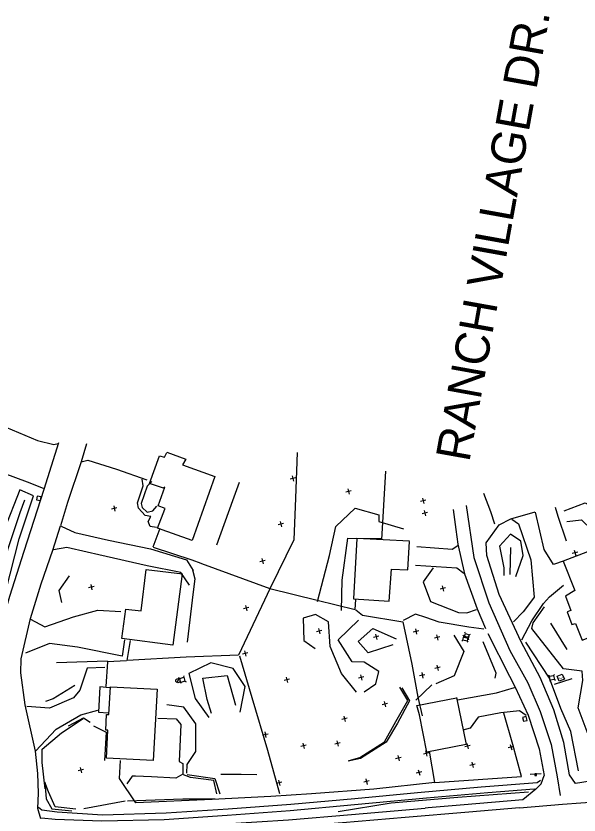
# Model space of a CAD drawing. Extents: x 4711259 to 4716401, y 890074 to 892728.
# Drawn here: x 4715293 to 4715801, y 891237 to 891958 of the extents above; entities that cross this region are included whole.
import ezdxf

# ---------------------------------------------------------------- set-up
doc = ezdxf.new("R2010")
doc.units = 0
for name, color, linetype in [('E_RDWY_PHOTOG_Eave', 7, 'Continuous'), ('E_RDWY_PHOTOG_Fence', 7, 'Continuous'), ('E_RDWY_ROAD_Approach', 7, 'Continuous'), ('E_RDWY_ROAD_Bikeway', 7, 'Continuous'), ('E_RDWY_ROAD_EdgeAsph', 7, 'Continuous'), ('E_RDWY_ROAD_EdgeConc', 7, 'Continuous'), ('E_RDWY_ROAD_EdgeGravel', 7, 'Continuous'), ('E_RDWY_ROAD_Mailbox', 7, 'Continuous'), ('E_RDWY_ROAD_NameTx', 7, 'Continuous'), ('E_RDWY_ROAD_Sidewalk', 7, 'Continuous'), ('E_RDWY_ROAD_Striping', 7, 'Continuous'), ('E_TERR_DTM_BrkLines', 7, 'Continuous'), ('E_TERR_DTM_RandomPt', 7, 'Continuous'), ('E_TRAF_SIGN_PublicSign', 7, 'Continuous'), ('E_UTIL_ELEC_GENERAL', 7, 'Continuous'), ('E_UTIL_WTR_General', 7, 'Continuous')]:
    doc.layers.add(name, color=color, linetype=linetype)

msp = doc.modelspace()

# ---------------------------------------------------------------- linework, layer by layer
at = {"layer": 'E_RDWY_PHOTOG_Eave'}
for points in [[(4715429.2, 891564.09), (4715446.53, 891557.78), (4715443.43, 891552.65), (4715472.58, 891542.14), (4715452.01, 891484.39), (4715420.98, 891495.61), (4715427.36, 891512.64), (4715427.8, 891513.27), (4715421.43, 891515.78), (4715427.63, 891532.73), (4715426.21, 891531.66), (4715413.64, 891536.07), (4715422.69, 891560.92), (4715427.2, 891559.56), (4715429.23, 891563.88)], [(4715648.14, 891483.86), (4715600.66, 891486.32), (4715597.69, 891431.8), (4715629.7, 891429.79), (4715631.79, 891458.79), (4715646.66, 891457.93), (4715648.21, 891483.75)], [(4715823.08, 891447.64), (4715812.44, 891475.7), (4715786.7, 891465.95), (4715797.08, 891439.28), (4715788.84, 891434.37), (4715793.61, 891421.39), (4715790.2, 891420.12), (4715794.34, 891408.79), (4715797.79, 891409.77), (4715803.67, 891394.65), (4715832.92, 891406.14), (4715817.58, 891445.43), (4715823.21, 891447.66)], [(4715443.19, 891454.37), (4715434.85, 891390.19), (4715388.76, 891396.18), (4715392.24, 891422.71), (4715406.06, 891421.09), (4715410.63, 891458.48), (4715443.34, 891454.32)], [(4715377.68, 891351.75), (4715368.85, 891352.41), (4715367.81, 891329.7), (4715376.54, 891329.14)], [(4715374.79, 891288.32), (4715376.11, 891313.42), (4715374.39, 891313.49), (4715374.9, 891327.49), (4715377, 891327.55), (4715378.41, 891352.46), (4715420.51, 891350.42), (4715416.94, 891286.21), (4715374.92, 891288.28)], [(4715690.52, 891342.82), (4715699.08, 891300.48), (4715663.61, 891293.5), (4715657.12, 891327.14), (4715654.87, 891335.71), (4715690.41, 891342.59)]]:
    msp.add_lwpolyline(points, dxfattribs=at)
at = {"layer": 'E_RDWY_PHOTOG_Fence'}
for points in [[(4715546.93, 891563.76), (4715545.29, 891522.84), (4715543.71, 891484.99), (4715522.62, 891441.43), (4715493.98, 891380.98), (4715446.79, 891379.25), (4715393.67, 891376.31), (4715396.49, 891394.27)], [(4715626.36, 891547.11), (4715622.79, 891485.32)], [(4715422.99, 891495.25), (4715416.82, 891478.64)], [(4715417.04, 891478.52), (4715451.97, 891467.24), (4715460.09, 891464.08), (4715460.57, 891463.88), (4715522.26, 891441.11), (4715564.96, 891430.62), (4715599.17, 891422.18), (4715599.63, 891431.37)], [(4715599.63, 891421.88), (4715605.68, 891417.08), (4715641.99, 891411.02), (4715650.16, 891373.08), (4715655.6, 891343.17)], [(4715494.86, 891380.52), (4715506.04, 891342.89), (4715520.14, 891295.46), (4715530.79, 891256.41)], [(4715375.75, 891375.66), (4715329.74, 891374.32)], [(4715392.91, 891376.05), (4715375.79, 891375.21), (4715374.28, 891352.86)], [(4715655.6, 891343.24), (4715659.65, 891326.49)], [(4715670.8, 891266.14), (4715749.04, 891271.51), (4715741.21, 891300.62), (4715733.16, 891328.73)], [(4715670.8, 891266.14), (4715666.17, 891294.66)], [(4715670.8, 891266.14), (4715615.95, 891260.34), (4715559.71, 891256.16), (4715523.12, 891253.62), (4715470.31, 891250.8), (4715401.33, 891248.03), (4715386.66, 891269.84), (4715387.49, 891286.18)]]:
    msp.add_lwpolyline(points, dxfattribs=at)
at = {"layer": 'E_RDWY_ROAD_Approach'}
for points in [[(4715252.03, 891599.9), (4715284.18, 891586.86), (4715312.84, 891574.65), (4715327.41, 891571.06), (4715331.38, 891572.16)], [(4715352.19, 891555.61), (4715357.99, 891556.98), (4715383.93, 891548.72), (4715411.14, 891539.1)], [(4715318.23, 891531.34), (4715303.81, 891537.16), (4715271.95, 891549.01), (4715265.44, 891547.1)], [(4715787.64, 891466.3), (4715778.01, 891463.02), (4715769.47, 891476.46), (4715761.57, 891509.99)], [(4715740.36, 891503.83), (4715746.52, 891499.51), (4715757.54, 891467.03), (4715760.46, 891433.33), (4715755.39, 891426.46), (4715750.69, 891420.07), (4715741.97, 891411.02)], [(4715333.97, 891497.57), (4715346.36, 891491.81), (4715376.83, 891484.73), (4715414.68, 891476.99)], [(4715691.72, 891479.68), (4715686.65, 891476.42), (4715654.84, 891478.69)], [(4715411.56, 891461.66), (4715368.07, 891471.71), (4715357.44, 891474.13), (4715339.08, 891478.3), (4715327.08, 891476)], [(4715414.68, 891476.99), (4715446.94, 891467.06), (4715453.02, 891457.48)], [(4715449.61, 891444.21), (4715441.87, 891455.64), (4715411.56, 891461.66)], [(4715653.56, 891462.33), (4715690.75, 891459.83), (4715697.09, 891455.14)], [(4715749.38, 891395.01), (4715758.36, 891412.09), (4715769.03, 891427.74), (4715774.2, 891433.57), (4715787, 891444.25)], [(4715306.52, 891413.65), (4715319.21, 891406.52), (4715345.25, 891415.53), (4715367.15, 891421.6), (4715387.9, 891420.48)], [(4715391.09, 891394.83), (4715388.99, 891380.08), (4715348.76, 891388.18), (4715323.42, 891391.61), (4715302, 891383.03)], [(4715373.51, 891369.92), (4715357.44, 891369.27), (4715350.98, 891349.67), (4715345.25, 891342.76), (4715323.38, 891333.18), (4715302.99, 891334.92)], [(4715691.47, 891340.87), (4715726.63, 891347.09), (4715742.85, 891351.91)], [(4715310.88, 891294.66), (4715329.57, 891314.31), (4715351.75, 891327.24), (4715366.96, 891331.49)], [(4715753.34, 891326.6), (4715747.2, 891331.04), (4715730.46, 891329.14), (4715709.99, 891325.07), (4715702.71, 891315.28), (4715696.15, 891313.37)]]:
    msp.add_lwpolyline(points, dxfattribs=at)
at = {"layer": 'E_RDWY_ROAD_Bikeway'}
for points in [[(4715273.98, 891372.25), (4715277.94, 891400.65), (4715287.62, 891434.44), (4715300.53, 891475.01), (4715318.78, 891530.92)], [(4715313.69, 891243.92), (4715316.49, 891241.6), (4715330.33, 891239.69), (4715371.17, 891237.13), (4715428.57, 891238.85), (4715484.55, 891242.36), (4715541.22, 891246.73), (4715598.7, 891251.85), (4715655.22, 891257.19), (4715712.77, 891262.41), (4715763.11, 891266.37), (4715766.2, 891268.43)], [(4715761.78, 891260.06), (4715760.61, 891260.12), (4715718.68, 891256.93), (4715663.31, 891252.09), (4715598.39, 891246.08), (4715540.62, 891240.77), (4715483.75, 891236.34), (4715426.99, 891232.63), (4715370.72, 891231.33), (4715328.5, 891232.91), (4715316.43, 891233.99)]]:
    msp.add_lwpolyline(points, dxfattribs=at)
at = {"layer": 'E_RDWY_ROAD_EdgeAsph'}
for points in [[(4715318.78, 891530.92), (4715332.08, 891572.97)], [(4715356.89, 891571.84), (4715352.04, 891555.56), (4715339.76, 891518.75), (4715333.43, 891497.68)], [(4715687.55, 891512.47), (4715689.97, 891494.41), (4715691.8, 891481.21), (4715697.67, 891454.4), (4715709.12, 891422.93), (4715716.58, 891405.12)], [(4715765.82, 891361.06), (4715748.67, 891393.16), (4715728.81, 891435.72), (4715717.7, 891471.13), (4715717.23, 891482.4), (4715728.86, 891498.55), (4715739.35, 891504.19), (4715761.28, 891510.49)], [(4715315.77, 891233.57), (4715312.94, 891242.69), (4715313.46, 891256.68), (4715312.87, 891274.28), (4715310.83, 891294.38), (4715301.47, 891336.28), (4715297.58, 891365.21), (4715298.06, 891377.67), (4715306.35, 891414.08), (4715315.97, 891445.5), (4715326.54, 891475.87), (4715333.43, 891497.68)], [(4715718.67, 891400.69), (4715738.16, 891362.18), (4715743.36, 891352.26), (4715755, 891327.06), (4715765.16, 891296.7), (4715769.4, 891272.55)], [(4715946.27, 891283.32), (4715908.75, 891277.38), (4715880.55, 891274.35), (4715834.17, 891270.55), (4715810.88, 891267.49), (4715797.7, 891265.23), (4715792.3, 891273.26), (4715787.25, 891302.4), (4715778.2, 891331.67), (4715765.82, 891361.06)], [(4715761.89, 891260.14), (4715766.88, 891264.9), (4715769.4, 891272.55)], [(4715761.89, 891260.14), (4715750.21, 891250.75), (4715697.43, 891246.05), (4715665.08, 891243.31), (4715662.3, 891243.21)], [(4715409.6, 891226.77), (4715425.01, 891226.45), (4715481.8, 891228.87), (4715539.04, 891232.52), (4715595.96, 891237.39), (4715662.3, 891243.21)]]:
    msp.add_lwpolyline(points, dxfattribs=at)
at = {"layer": 'E_RDWY_ROAD_EdgeConc'}
for points in [[(4715421.34, 891324.31), (4715437.86, 891323.59), (4715441.82, 891318.61), (4715440.39, 891285.08), (4715443.79, 891283.31), (4715443.6, 891273.8), (4715437.3, 891270.07), (4715415.5, 891271.24)], [(4715415.5, 891271.24), (4715400.96, 891271.82), (4715398.15, 891271.86), (4715393.31, 891265.04)]]:
    msp.add_lwpolyline(points, dxfattribs=at)
at = {"layer": 'E_RDWY_ROAD_EdgeGravel'}
for points in [[(4715787.64, 891511.17), (4715806.49, 891518.42), (4715825.64, 891507.92), (4715834.85, 891497.4)], [(4715779.39, 891514.45), (4715782, 891506.58), (4715789.46, 891484.14)], [(4715669.4, 891459.92), (4715660.42, 891447.18), (4715666.94, 891429.51), (4715692.16, 891419.53), (4715699.94, 891419.19), (4715708.49, 891422.25)], [(4715715.04, 891404.64), (4715701.63, 891406.32), (4715674.76, 891410.72), (4715662.69, 891415.15), (4715653.57, 891418.07), (4715642.3, 891412.4)], [(4715688.16, 891399.05), (4715697.15, 891384.53), (4715688.32, 891362.35), (4715671.96, 891355.28)], [(4715725.37, 891360.48), (4715726.25, 891364.92), (4715714.56, 891393.22)]]:
    msp.add_lwpolyline(points, dxfattribs=at)
at = {"layer": 'E_RDWY_ROAD_Mailbox'}
for points in [[(4715315.32, 891520.49), (4715315.9, 891523.95), (4715312.45, 891524.53), (4715311.86, 891521.08)], [(4715754.26, 891322.29), (4715753.41, 891325.68), (4715750.01, 891324.83), (4715750.87, 891321.43)]]:
    msp.add_lwpolyline(points, close=True, dxfattribs=at)
at = {"layer": 'E_RDWY_ROAD_Sidewalk'}
for points in [[(4715420.1, 891496.38), (4715414.24, 891497.25), (4715412.38, 891501.67), (4715414.81, 891506.29), (4715409.82, 891507.11), (4715403.64, 891513.63), (4715402.93, 891518.48), (4715407.83, 891533.72), (4715407.14, 891539.87)], [(4715415.76, 891537.63), (4715411.56, 891533.39), (4715406.17, 891518.04), (4715407.03, 891514.16), (4715411.61, 891510.12), (4715416.74, 891511.16), (4715420.35, 891515.55)], [(4715454.92, 891449.74), (4715452.78, 891457.62)]]:
    msp.add_lwpolyline(points, dxfattribs=at)
at = {"layer": 'E_RDWY_ROAD_Striping'}
msp.add_lwpolyline([(4715747.32, 891243.49), (4715701.5, 891239.6), (4715644.11, 891234.72), (4715587.74, 891229.82), (4715530.75, 891225.39), (4715474.19, 891221.81), (4715417.61, 891220.88), (4715364.79, 891222.96)], dxfattribs=at)
at = {"layer": 'E_TERR_DTM_BrkLines'}
for points in [[(4715474.29, 891480.59), (4715488.97, 891520.66), (4715494.77, 891537.08)], [(4715271.91, 891405.09), (4715284.11, 891438.92), (4715296.32, 891486), (4715309.02, 891524.84), (4715296.84, 891530.1), (4715282.62, 891494.11), (4715269.88, 891454.47), (4715261.02, 891414.77)], [(4715725.02, 891499.25), (4715721.42, 891510.26), (4715715.09, 891526.89)], [(4715267.5, 891409.9), (4715277.1, 891447.11), (4715286.22, 891477.41), (4715297.03, 891509.65), (4715301.43, 891521.2)], [(4715699.24, 891516.15), (4715706.07, 891469.29), (4715719.74, 891428.4), (4715738.49, 891385.28), (4715754.76, 891356.25), (4715765.78, 891330.33), (4715775.78, 891300.44), (4715781.34, 891271.41), (4715784.04, 891254.57)], [(4715565.17, 891429.61), (4715576.09, 891470.9), (4715581.7, 891497.25), (4715599.21, 891513.69), (4715620.33, 891507.76), (4715620.56, 891501.74), (4715642.61, 891495.1)], [(4715789.98, 891501.52), (4715803.17, 891503.23), (4715822.88, 891483.84), (4715855.77, 891461.12), (4715882.09, 891466.44), (4715900.72, 891477.97), (4715901.3, 891488.53)], [(4715586.9, 891421.38), (4715587.28, 891448.8), (4715592.65, 891486.63), (4715622.92, 891486.27)], [(4715744.12, 891452.04), (4715750.5, 891470.91), (4715748.62, 891483.94), (4715739.14, 891490.34), (4715729.21, 891479.55), (4715733.26, 891459.94), (4715733.1, 891452.89)], [(4715739.26, 891478.35), (4715738.62, 891453.77)], [(4715341.11, 891452.57), (4715332.03, 891439.37), (4715334.2, 891428.53)], [(4715447.86, 891392.88), (4715453.5, 891438.08), (4715454.94, 891449.82)], [(4715815.65, 891289.61), (4715809.18, 891309.66), (4715800.3, 891333.74), (4715804.47, 891358.27), (4715803.9, 891366.72), (4715786.85, 891368.84), (4715758.51, 891405.07), (4715759.74, 891410.3), (4715769.77, 891424.61)], [(4715600.34, 891347.76), (4715586.66, 891364.53), (4715576.57, 891388.91), (4715575, 891411.06), (4715563.25, 891417.79), (4715552.24, 891414.58), (4715552.71, 891394.41), (4715563.01, 891387.26)], [(4715607.14, 891347.99), (4715617.74, 891355.26), (4715620.56, 891366.51), (4715607.1, 891374.79), (4715596.28, 891375.12), (4715583.87, 891395), (4715602.14, 891412.79)], [(4715775.34, 891409.85), (4715790.11, 891386.36)], [(4715632.99, 891390.54), (4715610.87, 891383.28), (4715601.93, 891393.47), (4715614.98, 891405.13), (4715636.05, 891395.87)], [(4715800.51, 891276.82), (4715793.58, 891312.16), (4715784.41, 891333.04), (4715774.2, 891360.27), (4715752.99, 891392.89)], [(4715495.41, 891329.78), (4715500, 891352.71), (4715488.98, 891369.01), (4715469.02, 891374.27), (4715449.27, 891364.54), (4715454.99, 891341.9), (4715467.25, 891324.89)], [(4715469.71, 891328.35), (4715465.79, 891341.15), (4715461.66, 891360.22), (4715483.66, 891362.77), (4715491.28, 891335.94)], [(4715794.39, 891359.68), (4715778.64, 891354.72)], [(4715346.48, 891353.86), (4715326.88, 891341.58), (4715319.93, 891339.29)], [(4715641.1, 891351.58), (4715648.23, 891339.99), (4715637.18, 891319.89), (4715626.95, 891302.5), (4715603.91, 891287.92), (4715592.73, 891285.54)], [(4715593.81, 891286.04), (4715603.36, 891288.85), (4715625.49, 891302.89), (4715635.64, 891321.34), (4715646.63, 891340.08), (4715639.3, 891352.24)], [(4715653.94, 891340.61), (4715668.17, 891354.43)], [(4715447.45, 891274.79), (4715447.79, 891282.58), (4715455.34, 891294.33), (4715455.5, 891319.03), (4715444.49, 891334.08), (4715429.2, 891336.19)], [(4715319.61, 891260.39), (4715316.96, 891284.19), (4715316.89, 891296.17), (4715334.28, 891311.07), (4715353.87, 891324.07)], [(4715340.73, 891317.27), (4715354.11, 891324.67), (4715360.31, 891320.57)], [(4715363.22, 891317.36), (4715374.66, 891311.63), (4715373.21, 891286.15)], [(4715474.5, 891256.17), (4715471.8, 891268), (4715450.64, 891270.64), (4715444.23, 891273.28)], [(4715447.54, 891273.52), (4715472.65, 891269.78), (4715476.96, 891256.11)], [(4715510.43, 891273.03), (4715496.35, 891273.45), (4715478.03, 891273.4)], [(4715347.39, 891242.17), (4715328.54, 891244.29), (4715322.69, 891257.76), (4715319.41, 891266.49), (4715320.41, 891251.39), (4715325.53, 891242.35), (4715343.6, 891240.69)], [(4715755.31, 891257.57), (4715691.8, 891252.83), (4715631.67, 891247.46), (4715583.83, 891239.9)], [(4715391.77, 891249.46), (4715354.53, 891242.58)], [(4715393.82, 891249.86), (4715443.78, 891251.42), (4715472.8, 891251.62)], [(4715747.32, 891243.49), (4715786.14, 891246.67), (4715819.19, 891249.25)]]:
    msp.add_lwpolyline(points, dxfattribs=at)
at = {"layer": 'E_TERR_DTM_RandomPt'}
for p, q in [((4715545.45, 891540.97), (4715540.61, 891539.74)), ((4715542.41, 891542.78), (4715543.64, 891537.93)), ((4715592.54, 891531.25), (4715593.77, 891526.4)), ((4715595.58, 891529.44), (4715590.74, 891528.21)), ((4715659.71, 891522.72), (4715660.94, 891517.87)), ((4715381.39, 891515.86), (4715382.48, 891510.98)), ((4715662.75, 891520.91), (4715657.9, 891519.68)), ((4715384.38, 891513.96), (4715379.5, 891512.87)), ((4715664.3, 891509.7), (4715659.46, 891508.47)), ((4715661.26, 891511.51), (4715662.5, 891506.66)), ((4715531.39, 891501.56), (4715532.62, 891496.71)), ((4715534.43, 891499.75), (4715529.58, 891498.52)), ((4715799.74, 891474.13), (4715794.9, 891472.9)), ((4715796.7, 891475.94), (4715797.94, 891471.09)), ((4715518.05, 891466.46), (4715513.2, 891465.23)), ((4715515.01, 891468.27), (4715516.24, 891463.42)), ((4715360.68, 891444.9), (4715361.77, 891440.02)), ((4715677.65, 891443.78), (4715678.88, 891438.94)), ((4715363.67, 891443), (4715358.79, 891441.91)), ((4715680.68, 891441.98), (4715675.84, 891440.75)), ((4715503.14, 891424.07), (4715498.29, 891422.84)), ((4715500.1, 891425.88), (4715501.33, 891421.03)), ((4715569.03, 891403.26), (4715564.18, 891402.03)), ((4715565.99, 891405.07), (4715567.22, 891400.22)), ((4715617.4, 891400.09), (4715618.63, 891395.25)), ((4715656.39, 891402.97), (4715651.51, 891401.88)), ((4715653.4, 891404.86), (4715654.49, 891399.98)), ((4715620.44, 891398.28), (4715615.6, 891397.06)), ((4715675.5, 891397.55), (4715670.65, 891396.32)), ((4715672.46, 891399.36), (4715673.69, 891394.51)), ((4715502.33, 891383.18), (4715497.48, 891381.96)), ((4715499.29, 891384.99), (4715500.52, 891380.15)), ((4715672.7, 891371.98), (4715673.93, 891367.14)), ((4715659.09, 891365.37), (4715660.18, 891360.49)), ((4715675.74, 891370.18), (4715670.89, 891368.95)), ((4715540.01, 891359.45), (4715535.16, 891358.22)), ((4715536.97, 891361.26), (4715538.2, 891356.41)), ((4715606.83, 891361.52), (4715601.98, 891360.29)), ((4715603.79, 891363.33), (4715605.02, 891358.48)), ((4715662.07, 891363.48), (4715657.19, 891362.39)), ((4715628.18, 891337.39), (4715623.34, 891336.16)), ((4715625.15, 891339.2), (4715626.38, 891334.35)), ((4715591.88, 891324.35), (4715587.03, 891323.12)), ((4715588.84, 891326.16), (4715590.07, 891321.31)), ((4715520.57, 891309.94), (4715515.69, 891308.85)), ((4715517.58, 891311.84), (4715518.67, 891306.96)), ((4715554.98, 891300.01), (4715550.13, 891298.78)), ((4715551.94, 891301.82), (4715553.17, 891296.98)), ((4715585.57, 891302.03), (4715580.72, 891300.8)), ((4715582.53, 891303.83), (4715583.76, 891298.99)), ((4715702.92, 891299.59), (4715698.07, 891298.35)), ((4715699.88, 891301.39), (4715701.11, 891296.55)), ((4715739.01, 891300.51), (4715740.25, 891295.66)), ((4715665.54, 891293), (4715660.69, 891291.77)), ((4715662.5, 891294.81), (4715663.73, 891289.96)), ((4715742.05, 891298.7), (4715737.21, 891297.47)), ((4715640.47, 891288.81), (4715635.63, 891287.58)), ((4715637.44, 891290.62), (4715638.67, 891285.77)), ((4715704.22, 891284.53), (4715705.45, 891279.68)), ((4715354.18, 891277.96), (4715349.3, 891276.87)), ((4715351.19, 891279.85), (4715352.28, 891274.97)), ((4715656.05, 891277.7), (4715657.28, 891272.85)), ((4715707.26, 891282.72), (4715702.41, 891281.49)), ((4715659.09, 891275.89), (4715654.24, 891274.66)), ((4715532.99, 891266.56), (4715528.11, 891265.47)), ((4715530.01, 891268.45), (4715531.1, 891263.57)), ((4715611.74, 891267.63), (4715606.89, 891266.4)), ((4715608.7, 891269.44), (4715609.93, 891264.59))]:
    msp.add_line(p, q, dxfattribs=at)
at = {"layer": 'E_TRAF_SIGN_PublicSign'}
for p, q in [((4715756.89, 891273.66), (4715766.87, 891274.27)), ((4715761.92, 891273.22), (4715761.92, 891273.22))]:
    msp.add_line(p, q, dxfattribs=at)
msp.add_lwpolyline([(4715761.13, 891273.92), (4715761.22, 891272.42), (4715762.72, 891272.51), (4715762.63, 891274.01)], close=True, dxfattribs=at)
at = {"layer": 'E_UTIL_ELEC_GENERAL'}
msp.add_lwpolyline([(4715783.1, 891357.58), (4715781.23, 891362.22), (4715785.87, 891364.09), (4715787.74, 891359.45)], close=True, dxfattribs=at)
at = {"layer": 'E_UTIL_WTR_General'}
for p, q in [((4715698.46, 891400.71), (4715697.92, 891401.75)), ((4715702.04, 891399.58), (4715703.09, 891400.12)), ((4715696.3, 891394.49), (4715695.34, 891393.82)), ((4715696.95, 891398.19), (4715696.27, 891399.15)), ((4715697.33, 891397.13), (4715696.29, 891396.59)), ((4715699.99, 891393.84), (4715700.67, 891392.88)), ((4715700.64, 891397.54), (4715701.61, 891398.21)), ((4715700.91, 891396), (4715701.45, 891394.95)), ((4715438.51, 891356.41), (4715440.06, 891359.83)), ((4715440.96, 891360.18), (4715439.92, 891360.73)), ((4715442.07, 891356.59), (4715441.52, 891355.55)), ((4715444.54, 891361.28), (4715445.09, 891362.33)), ((4715445.65, 891357.7), (4715446.69, 891357.15)), ((4715774.38, 891362.09), (4715773.41, 891362.76)), ((4715775.08, 891358.41), (4715774.41, 891357.44)), ((4715778.07, 891362.79), (4715778.73, 891363.76)), ((4715778.76, 891359.1), (4715779.74, 891358.44))]:
    msp.add_line(p, q, dxfattribs=at)
for points in [[(4715697.33, 891397.13), (4715698.46, 891400.71), (4715702.04, 891399.58), (4715700.91, 891396)], [(4715696.95, 891398.19), (4715700.64, 891397.54), (4715699.99, 891393.84), (4715696.3, 891394.49)], [(4715442.07, 891356.59), (4715440.96, 891360.18), (4715444.54, 891361.28), (4715445.65, 891357.7)], [(4715775.08, 891358.41), (4715774.38, 891362.09), (4715778.07, 891362.79), (4715778.76, 891359.1)]]:
    msp.add_lwpolyline(points, close=True, dxfattribs=at)
msp.add_circle((4715439.28, 891358.12), 1.87, dxfattribs=at)

# ---------------------------------------------------------------- texts
at = {"layer": 'E_RDWY_ROAD_NameTx'}
msp.add_text('RANCH VILLAGE DR.', height=30.8399, rotation=79.79937, dxfattribs=at).set_placement((4715701.96, 891554.51))
at = {"layer": 'E_UTIL_ELEC_GENERAL'}
msp.add_text('J', height=3, rotation=291.92819, dxfattribs=at).set_placement((4715782.71, 891361.04))

doc.saveas('drawing.dxf')
